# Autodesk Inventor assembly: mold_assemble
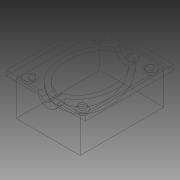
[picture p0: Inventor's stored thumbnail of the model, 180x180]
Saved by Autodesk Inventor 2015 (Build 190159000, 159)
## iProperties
Created: 2015-04
Part Number: mold_assemble
Document SubType Name: Assembly
Designer: sungeun
Author: sungeun
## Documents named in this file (3)
- \\psf\Home\Desktop\mold_assemble.iam
- \\psf\Home\Desktop\mold_bottom.ipt
- \\psf\Home\Desktop\mold_top.ipt
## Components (2 placed, 2 different names)
1. mold_bottom:1 — Mate:1, Flush:1, Flush:2
2. mold_top:1 — Mate:1, Flush:1, Flush:2
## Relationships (3: Flush 2, Mate 1)
- Mate:1: mold_bottom:1 ↔ mold_top:1
- Flush:1: mold_bottom:1 ↔ mold_top:1
- Flush:2: mold_bottom:1 ↔ mold_top:1
